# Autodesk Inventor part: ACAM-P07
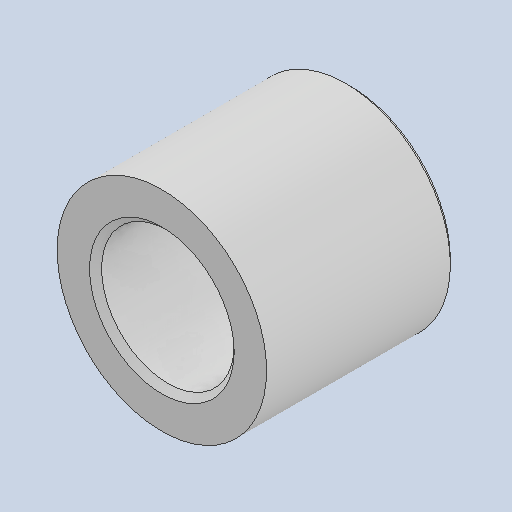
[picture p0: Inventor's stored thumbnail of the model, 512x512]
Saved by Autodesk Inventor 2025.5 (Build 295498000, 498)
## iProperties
Company: Open CASCADE
Created: 2026-10
Part Number: ACAM-P07
Material: Genérico
Description: Casquillo M8
Document SubType Name: Modeling
Designer: Luis M
Authority: Unknown
Density: 1 g/cm^3
Appearance: Valor por defecto
Sending System: Open CASCADE 7.9
Preprocessor: Open CASCADE STEP processor 7.9
Material_BOM: PLA
Proceso_BOM: Impresión 3D
Title: Open CASCADE Shape Model
Author: Author
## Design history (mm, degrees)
feature "Base1"
node "Sólido1"
